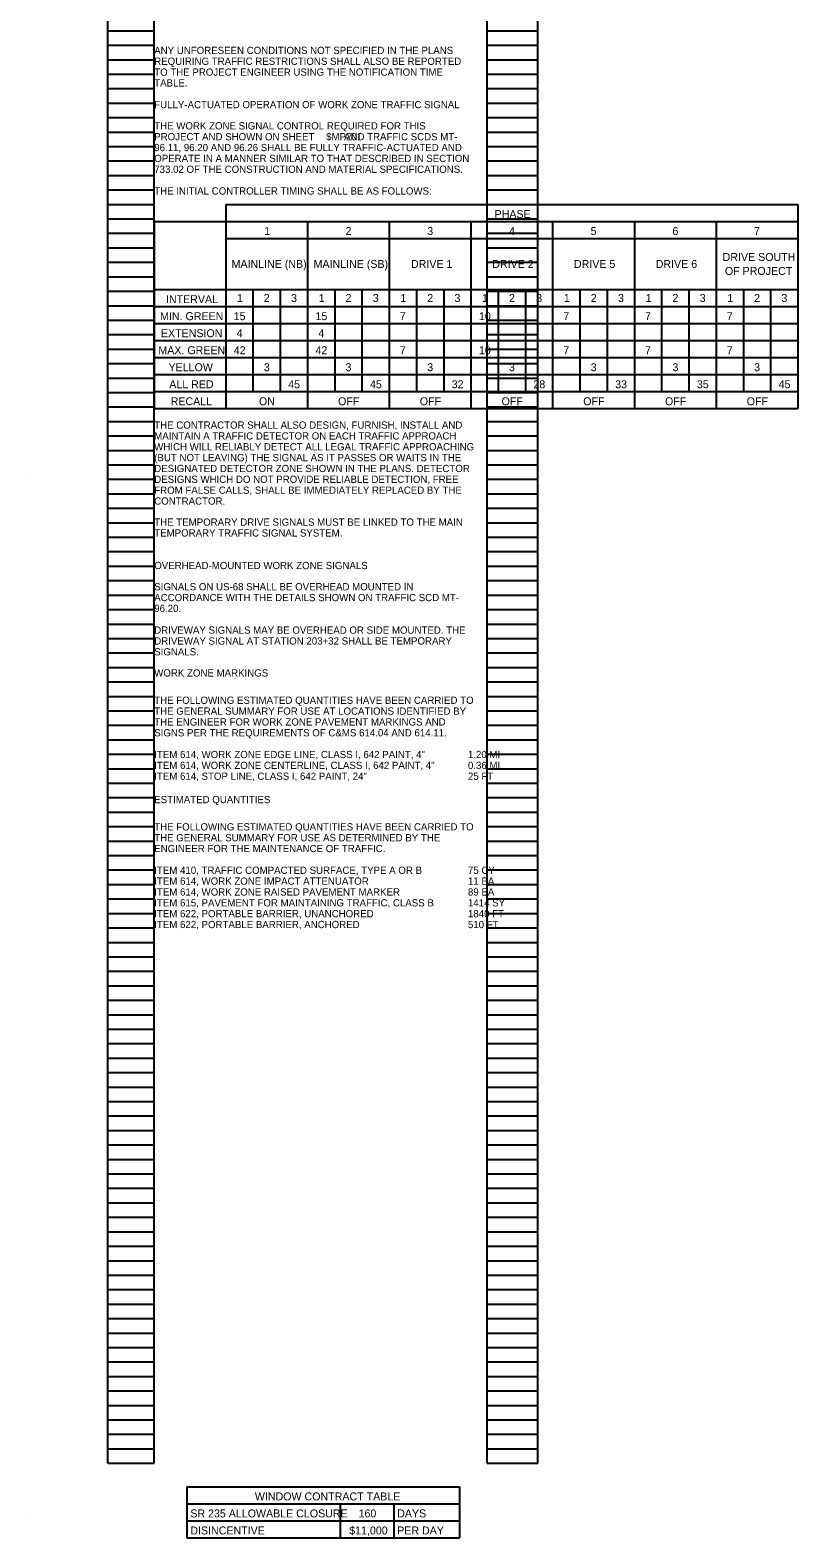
# Model space of a CAD drawing. Extents: x 11124 to 11156, y 1608 to 1730.
# Drawn here: x 11124.4 to 11139.25, y 1607.81 to 1636.98 of the extents above; entities that cross this region are included whole.
import ezdxf

# ---------------------------------------------------------------- set-up
doc = ezdxf.new("R2010")
doc.units = 0
for name, color, linetype in [('SC_Scratch1', 7, 'Continuous'), ('SH_Data', 7, 'Continuous'), ('SH_Text', 7, 'Continuous')]:
    doc.layers.add(name, color=color, linetype=linetype)

msp = doc.modelspace()

# ---------------------------------------------------------------- linework, layer by layer
at = {"layer": 'SC_Scratch1'}
for p, q in [((11125.896, 1629.409), (11125.896, 1649.569)), ((11126.796, 1629.409), (11126.796, 1649.569)), ((11133.236, 1629.409), (11133.236, 1649.569)), ((11134.216, 1629.409), (11134.216, 1649.569)), ((11125.896, 1636.969), (11126.796, 1636.969)), ((11133.236, 1636.969), (11134.216, 1636.969)), ((11125.896, 1636.689), (11126.796, 1636.689)), ((11133.236, 1636.689), (11134.216, 1636.689)), ((11125.896, 1636.409), (11126.796, 1636.409)), ((11133.236, 1636.409), (11134.216, 1636.409)), ((11125.896, 1636.129), (11126.796, 1636.129)), ((11133.236, 1636.129), (11134.216, 1636.129)), ((11125.896, 1635.849), (11126.796, 1635.849)), ((11125.896, 1635.569), (11126.796, 1635.569)), ((11133.236, 1635.849), (11134.216, 1635.849)), ((11133.236, 1635.569), (11134.216, 1635.569)), ((11125.896, 1635.289), (11126.796, 1635.289)), ((11133.236, 1635.289), (11134.216, 1635.289)), ((11125.896, 1635.009), (11126.796, 1635.009)), ((11133.236, 1635.009), (11134.216, 1635.009)), ((11125.896, 1634.729), (11126.796, 1634.729)), ((11133.236, 1634.729), (11134.216, 1634.729)), ((11125.896, 1634.449), (11126.796, 1634.449)), ((11133.236, 1634.449), (11134.216, 1634.449)), ((11125.896, 1634.169), (11126.796, 1634.169)), ((11133.236, 1634.169), (11134.216, 1634.169)), ((11125.896, 1633.889), (11126.796, 1633.889)), ((11133.236, 1633.889), (11134.216, 1633.889)), ((11125.896, 1633.609), (11126.796, 1633.609)), ((11133.236, 1633.609), (11134.216, 1633.609)), ((11125.896, 1633.329), (11126.796, 1633.329)), ((11133.236, 1633.329), (11134.216, 1633.329)), ((11125.896, 1633.049), (11126.796, 1633.049)), ((11133.236, 1633.049), (11134.216, 1633.049)), ((11125.896, 1632.769), (11126.796, 1632.769)), ((11133.236, 1632.769), (11134.216, 1632.769)), ((11125.896, 1632.489), (11126.796, 1632.489)), ((11133.236, 1632.489), (11134.216, 1632.489)), ((11125.896, 1632.209), (11126.796, 1632.209)), ((11133.236, 1632.209), (11134.216, 1632.209)), ((11125.896, 1631.929), (11126.796, 1631.929)), ((11133.236, 1631.929), (11134.216, 1631.929)), ((11125.896, 1631.649), (11126.796, 1631.649)), ((11133.236, 1631.649), (11134.216, 1631.649)), ((11125.896, 1631.369), (11126.796, 1631.369)), ((11133.236, 1631.369), (11134.216, 1631.369)), ((11125.896, 1631.089), (11126.796, 1631.089)), ((11133.236, 1631.089), (11134.216, 1631.089)), ((11125.896, 1630.809), (11126.796, 1630.809)), ((11133.236, 1630.809), (11134.216, 1630.809)), ((11125.896, 1630.529), (11126.796, 1630.529)), ((11133.236, 1630.529), (11134.216, 1630.529)), ((11125.896, 1630.249), (11126.796, 1630.249)), ((11133.236, 1630.249), (11134.216, 1630.249)), ((11125.896, 1629.969), (11126.796, 1629.969)), ((11133.236, 1629.969), (11134.216, 1629.969)), ((11125.896, 1629.689), (11126.796, 1629.689)), ((11133.236, 1629.689), (11134.216, 1629.689)), ((11125.896, 1629.409), (11126.796, 1629.409)), ((11125.896, 1609.249), (11125.896, 1629.409)), ((11125.896, 1629.409), (11126.796, 1629.409)), ((11126.796, 1609.249), (11126.796, 1629.409)), ((11133.236, 1629.409), (11134.216, 1629.409)), ((11133.236, 1609.249), (11133.236, 1629.409)), ((11133.236, 1629.409), (11134.216, 1629.409)), ((11134.216, 1609.249), (11134.216, 1629.409)), ((11125.896, 1629.129), (11126.796, 1629.129)), ((11125.896, 1628.849), (11126.796, 1628.849)), ((11133.236, 1629.129), (11134.216, 1629.129)), ((11133.236, 1628.849), (11134.216, 1628.849)), ((11125.896, 1628.569), (11126.796, 1628.569)), ((11133.236, 1628.569), (11134.216, 1628.569)), ((11124.396, 1628.429), (11124.396, 1628.429)), ((11125.896, 1628.289), (11126.796, 1628.289)), ((11133.236, 1628.289), (11134.216, 1628.289)), ((11125.896, 1628.009), (11126.796, 1628.009)), ((11133.236, 1628.009), (11134.216, 1628.009)), ((11125.896, 1627.729), (11126.796, 1627.729)), ((11133.236, 1627.729), (11134.216, 1627.729)), ((11125.896, 1627.449), (11126.796, 1627.449)), ((11133.236, 1627.449), (11134.216, 1627.449)), ((11125.896, 1627.169), (11126.796, 1627.169)), ((11133.236, 1627.169), (11134.216, 1627.169)), ((11125.896, 1626.889), (11126.796, 1626.889)), ((11133.236, 1626.889), (11134.216, 1626.889)), ((11125.896, 1626.609), (11126.796, 1626.609)), ((11133.236, 1626.609), (11134.216, 1626.609)), ((11125.896, 1626.329), (11126.796, 1626.329)), ((11133.236, 1626.329), (11134.216, 1626.329)), ((11125.896, 1626.049), (11126.796, 1626.049)), ((11133.236, 1626.049), (11134.216, 1626.049)), ((11125.896, 1625.769), (11126.796, 1625.769)), ((11133.236, 1625.769), (11134.216, 1625.769)), ((11125.896, 1625.489), (11126.796, 1625.489)), ((11133.236, 1625.489), (11134.216, 1625.489)), ((11125.896, 1625.209), (11126.796, 1625.209)), ((11133.236, 1625.209), (11134.216, 1625.209)), ((11125.896, 1624.929), (11126.796, 1624.929)), ((11133.236, 1624.929), (11134.216, 1624.929)), ((11125.896, 1624.649), (11126.796, 1624.649)), ((11133.236, 1624.649), (11134.216, 1624.649)), ((11125.896, 1624.369), (11126.796, 1624.369)), ((11133.236, 1624.369), (11134.216, 1624.369)), ((11125.896, 1624.089), (11126.796, 1624.089)), ((11133.236, 1624.089), (11134.216, 1624.089)), ((11125.896, 1623.809), (11126.796, 1623.809)), ((11133.236, 1623.809), (11134.216, 1623.809)), ((11125.896, 1623.529), (11126.796, 1623.529)), ((11133.236, 1623.529), (11134.216, 1623.529)), ((11125.896, 1623.249), (11126.796, 1623.249)), ((11133.236, 1623.249), (11134.216, 1623.249)), ((11125.896, 1622.969), (11126.796, 1622.969)), ((11133.236, 1622.969), (11134.216, 1622.969)), ((11125.896, 1622.689), (11126.796, 1622.689)), ((11133.236, 1622.689), (11134.216, 1622.689)), ((11125.896, 1622.409), (11126.796, 1622.409)), ((11133.236, 1622.409), (11134.216, 1622.409)), ((11125.896, 1622.129), (11126.796, 1622.129)), ((11125.896, 1621.849), (11126.796, 1621.849)), ((11133.236, 1622.129), (11134.216, 1622.129)), ((11133.236, 1621.849), (11134.216, 1621.849)), ((11125.896, 1621.569), (11126.796, 1621.569)), ((11133.236, 1621.569), (11134.216, 1621.569)), ((11125.896, 1621.289), (11126.796, 1621.289)), ((11133.236, 1621.289), (11134.216, 1621.289)), ((11125.896, 1621.009), (11126.796, 1621.009)), ((11133.236, 1621.009), (11134.216, 1621.009)), ((11125.896, 1620.729), (11126.796, 1620.729)), ((11133.236, 1620.729), (11134.216, 1620.729)), ((11125.896, 1620.449), (11126.796, 1620.449)), ((11133.236, 1620.449), (11134.216, 1620.449)), ((11125.896, 1620.169), (11126.796, 1620.169)), ((11133.236, 1620.169), (11134.216, 1620.169)), ((11125.896, 1619.889), (11126.796, 1619.889)), ((11133.236, 1619.889), (11134.216, 1619.889)), ((11125.896, 1619.609), (11126.796, 1619.609)), ((11133.236, 1619.609), (11134.216, 1619.609)), ((11125.896, 1619.329), (11126.796, 1619.329)), ((11133.236, 1619.329), (11134.216, 1619.329)), ((11125.896, 1619.049), (11126.796, 1619.049)), ((11133.236, 1619.049), (11134.216, 1619.049)), ((11125.896, 1618.769), (11126.796, 1618.769)), ((11133.236, 1618.769), (11134.216, 1618.769)), ((11125.896, 1618.489), (11126.796, 1618.489)), ((11133.236, 1618.489), (11134.216, 1618.489)), ((11125.896, 1618.209), (11126.796, 1618.209)), ((11133.236, 1618.209), (11134.216, 1618.209)), ((11125.896, 1617.929), (11126.796, 1617.929)), ((11133.236, 1617.929), (11134.216, 1617.929)), ((11125.896, 1617.649), (11126.796, 1617.649)), ((11133.236, 1617.649), (11134.216, 1617.649)), ((11125.896, 1617.369), (11126.796, 1617.369)), ((11133.236, 1617.369), (11134.216, 1617.369)), ((11125.896, 1617.089), (11126.796, 1617.089)), ((11133.236, 1617.089), (11134.216, 1617.089)), ((11125.896, 1616.809), (11126.796, 1616.809)), ((11133.236, 1616.809), (11134.216, 1616.809)), ((11125.896, 1616.529), (11126.796, 1616.529)), ((11133.236, 1616.529), (11134.216, 1616.529)), ((11125.896, 1616.249), (11126.796, 1616.249)), ((11133.236, 1616.249), (11134.216, 1616.249)), ((11125.896, 1615.969), (11126.796, 1615.969)), ((11133.236, 1615.969), (11134.216, 1615.969)), ((11125.896, 1615.689), (11126.796, 1615.689)), ((11133.236, 1615.689), (11134.216, 1615.689)), ((11125.896, 1615.409), (11126.796, 1615.409)), ((11133.236, 1615.409), (11134.216, 1615.409)), ((11125.896, 1615.129), (11126.796, 1615.129)), ((11125.896, 1614.849), (11126.796, 1614.849)), ((11133.236, 1615.129), (11134.216, 1615.129)), ((11133.236, 1614.849), (11134.216, 1614.849)), ((11125.896, 1614.569), (11126.796, 1614.569)), ((11133.236, 1614.569), (11134.216, 1614.569)), ((11125.896, 1614.289), (11126.796, 1614.289)), ((11133.236, 1614.289), (11134.216, 1614.289)), ((11125.896, 1614.009), (11126.796, 1614.009)), ((11133.236, 1614.009), (11134.216, 1614.009)), ((11125.896, 1613.729), (11126.796, 1613.729)), ((11133.236, 1613.729), (11134.216, 1613.729)), ((11125.896, 1613.449), (11126.796, 1613.449)), ((11133.236, 1613.449), (11134.216, 1613.449)), ((11125.896, 1613.169), (11126.796, 1613.169)), ((11133.236, 1613.169), (11134.216, 1613.169)), ((11125.896, 1612.889), (11126.796, 1612.889)), ((11133.236, 1612.889), (11134.216, 1612.889)), ((11125.896, 1612.609), (11126.796, 1612.609)), ((11133.236, 1612.609), (11134.216, 1612.609)), ((11125.896, 1612.329), (11126.796, 1612.329)), ((11133.236, 1612.329), (11134.216, 1612.329)), ((11125.896, 1612.049), (11126.796, 1612.049)), ((11133.236, 1612.049), (11134.216, 1612.049)), ((11125.896, 1611.769), (11126.796, 1611.769)), ((11133.236, 1611.769), (11134.216, 1611.769)), ((11125.896, 1611.489), (11126.796, 1611.489)), ((11133.236, 1611.489), (11134.216, 1611.489)), ((11125.896, 1611.209), (11126.796, 1611.209)), ((11133.236, 1611.209), (11134.216, 1611.209)), ((11125.896, 1610.929), (11126.796, 1610.929)), ((11133.236, 1610.929), (11134.216, 1610.929)), ((11125.896, 1610.649), (11126.796, 1610.649)), ((11133.236, 1610.649), (11134.216, 1610.649)), ((11125.896, 1610.369), (11126.796, 1610.369)), ((11133.236, 1610.369), (11134.216, 1610.369)), ((11125.896, 1610.089), (11126.796, 1610.089)), ((11133.236, 1610.089), (11134.216, 1610.089)), ((11125.896, 1609.809), (11126.796, 1609.809)), ((11133.236, 1609.809), (11134.216, 1609.809)), ((11125.896, 1609.529), (11126.796, 1609.529)), ((11133.236, 1609.529), (11134.216, 1609.529)), ((11125.896, 1609.249), (11126.796, 1609.249)), ((11133.236, 1609.249), (11134.216, 1609.249)), ((11124.396, 1608.269), (11124.396, 1608.269))]:
    msp.add_line(p, q, dxfattribs=at)
at = {"layer": 'SH_Data'}
for p, q in [((11128.179, 1633.609), (11139.247, 1633.609)), ((11128.179, 1633.609), (11128.179, 1629.656)), ((11139.247, 1633.609), (11139.247, 1629.656)), ((11126.796, 1633.279), (11139.247, 1633.279)), ((11126.796, 1633.279), (11126.796, 1629.656)), ((11129.76, 1633.279), (11129.76, 1629.656)), ((11131.342, 1633.279), (11131.342, 1629.656)), ((11132.923, 1633.279), (11132.923, 1629.656)), ((11134.504, 1633.279), (11134.504, 1629.656)), ((11136.085, 1633.279), (11136.085, 1629.656)), ((11137.666, 1633.279), (11137.666, 1629.656)), ((11128.179, 1632.95), (11139.247, 1632.95)), ((11126.796, 1631.962), (11139.247, 1631.962)), ((11128.706, 1631.962), (11128.706, 1629.985)), ((11129.233, 1631.962), (11129.233, 1629.985)), ((11130.287, 1631.962), (11130.287, 1629.985)), ((11130.814, 1631.962), (11130.814, 1629.985)), ((11131.869, 1631.962), (11131.869, 1629.985)), ((11132.396, 1631.962), (11132.396, 1629.985)), ((11133.45, 1631.962), (11133.45, 1629.985)), ((11133.977, 1631.962), (11133.977, 1629.985)), ((11135.031, 1631.962), (11135.031, 1629.985)), ((11135.558, 1631.962), (11135.558, 1629.985)), ((11136.612, 1631.962), (11136.612, 1629.985)), ((11137.139, 1631.962), (11137.139, 1629.985)), ((11138.193, 1631.962), (11138.193, 1629.985)), ((11138.72, 1631.962), (11138.72, 1629.985)), ((11126.796, 1631.632), (11139.247, 1631.632)), ((11126.796, 1631.303), (11139.247, 1631.303)), ((11126.796, 1630.974), (11139.247, 1630.974)), ((11126.796, 1630.644), (11139.247, 1630.644)), ((11126.796, 1630.315), (11139.247, 1630.315)), ((11126.796, 1629.985), (11139.247, 1629.985)), ((11126.796, 1629.656), (11139.247, 1629.656)), ((11127.428, 1608.794), (11132.699, 1608.794)), ((11127.428, 1608.794), (11127.428, 1607.805)), ((11132.699, 1608.794), (11132.699, 1607.805)), ((11127.428, 1608.464), (11132.699, 1608.464)), ((11130.393, 1608.464), (11130.393, 1607.805)), ((11131.431, 1608.464), (11131.431, 1607.805)), ((11127.428, 1608.135), (11132.699, 1608.135)), ((11127.428, 1607.805), (11132.699, 1607.805))]:
    msp.add_line(p, q, dxfattribs=at)

# ---------------------------------------------------------------- texts
at = {"layer": 'SH_Text'}
for s, height, p in [('ANY UNFORESEEN CONDITIONS NOT SPECIFIED IN THE PLANS ', 0.14, (11126.796, 1636.519)), ('REQUIRING TRAFFIC RESTRICTIONS SHALL ALSO BE REPORTED ', 0.14, (11126.796, 1636.309)), ('TO THE PROJECT ENGINEER USING THE NOTIFICATION TIME ', 0.14, (11126.796, 1636.099)), ('TABLE.', 0.14, (11126.796, 1635.889)), ('FULLY-ACTUATED OPERATION OF WORK ZONE TRAFFIC SIGNAL', 0.14, (11126.796, 1635.469)), ('THE WORK ZONE SIGNAL CONTROL REQUIRED FOR THIS ', 0.14, (11126.796, 1635.059)), ('PROJECT AND SHOWN ON SHEET           AND TRAFFIC SCDS MT-', 0.14, (11126.796, 1634.849)), ('$MP201', 0.14, (11130.122, 1634.849)), ('96.11, 96.20 AND 96.26 SHALL BE FULLY TRAFFIC-ACTUATED AND ', 0.14, (11126.796, 1634.639)), ('OPERATE IN A MANNER SIMILAR TO THAT DESCRIBED IN SECTION ', 0.14, (11126.796, 1634.429)), ('733.02 OF THE CONSTRUCTION AND MATERIAL SPECIFICATIONS. ', 0.14, (11126.796, 1634.219)), ('THE INITIAL CONTROLLER TIMING SHALL BE AS FOLLOWS:', 0.14, (11126.796, 1633.799)), ('PHASE', 0.154, (11133.381, 1633.345)), ('1', 0.154, (11128.923, 1633.016)), ('2', 0.154, (11130.497, 1633.016)), ('3', 0.154, (11132.078, 1633.016)), ('4', 0.154, (11133.661, 1633.016)), ('5', 0.154, (11135.239, 1633.016)), ('6', 0.154, (11136.821, 1633.016)), ('7', 0.154, (11138.399, 1633.016)), ('DRIVE SOUTH ', 0.154, (11137.792, 1632.514)), ('MAINLINE (NB)', 0.154, (11128.292, 1632.379)), ('MAINLINE (SB)', 0.154, (11129.879, 1632.379)), ('DRIVE 1', 0.154, (11131.763, 1632.379)), ('DRIVE 2', 0.154, (11133.336, 1632.379)), ('DRIVE 5', 0.154, (11134.916, 1632.379)), ('DRIVE 6', 0.154, (11136.498, 1632.379)), ('OF PROJECT', 0.154, (11137.836, 1632.244)), ('INTERVAL', 0.154, (11127.024, 1631.698)), ('1', 0.154, (11128.396, 1631.72)), ('2', 0.154, (11128.915, 1631.72)), ('3', 0.154, (11129.443, 1631.72)), ('1', 0.154, (11129.978, 1631.72)), ('2', 0.154, (11130.497, 1631.72)), ('3', 0.154, (11131.024, 1631.72)), ('1', 0.154, (11131.559, 1631.72)), ('2', 0.154, (11132.078, 1631.72)), ('3', 0.154, (11132.605, 1631.72)), ('1', 0.154, (11133.14, 1631.72)), ('2', 0.154, (11133.659, 1631.72)), ('3', 0.154, (11134.186, 1631.72)), ('1', 0.154, (11134.721, 1631.72)), ('2', 0.154, (11135.24, 1631.72)), ('3', 0.154, (11135.768, 1631.72)), ('1', 0.154, (11136.302, 1631.72)), ('2', 0.154, (11136.821, 1631.72)), ('3', 0.154, (11137.349, 1631.72)), ('1', 0.154, (11137.883, 1631.72)), ('2', 0.154, (11138.402, 1631.72)), ('3', 0.154, (11138.93, 1631.72)), ('MIN. GREEN', 0.154, (11126.909, 1631.369)), ('15', 0.154, (11128.333, 1631.369)), ('15', 0.154, (11129.915, 1631.369)), ('7', 0.154, (11131.547, 1631.369)), ('10', 0.154, (11133.078, 1631.369)), ('7', 0.154, (11134.71, 1631.369)), ('7', 0.154, (11136.291, 1631.369)), ('7', 0.154, (11137.872, 1631.369)), ('EXTENSION', 0.154, (11126.925, 1631.039)), ('4', 0.154, (11128.39, 1631.039)), ('4', 0.154, (11129.971, 1631.039)), ('MAX. GREEN', 0.154, (11126.876, 1630.71)), ('42', 0.154, (11128.335, 1630.71)), ('42', 0.154, (11129.916, 1630.71)), ('7', 0.154, (11131.547, 1630.71)), ('10', 0.154, (11133.078, 1630.71)), ('7', 0.154, (11134.71, 1630.71)), ('7', 0.154, (11136.291, 1630.71)), ('7', 0.154, (11137.872, 1630.71)), ('YELLOW', 0.154, (11127.072, 1630.381)), ('3', 0.154, (11128.916, 1630.381)), ('3', 0.154, (11130.497, 1630.381)), ('3', 0.154, (11132.078, 1630.381)), ('3', 0.154, (11133.659, 1630.381)), ('3', 0.154, (11135.241, 1630.381)), ('3', 0.154, (11136.822, 1630.381)), ('3', 0.154, (11138.403, 1630.381)), ('ALL RED', 0.154, (11127.087, 1630.051)), ('45', 0.154, (11129.388, 1630.051)), ('45', 0.154, (11130.969, 1630.051)), ('32', 0.154, (11132.551, 1630.051)), ('28', 0.154, (11134.132, 1630.051)), ('33', 0.154, (11135.714, 1630.051)), ('35', 0.154, (11137.294, 1630.051)), ('45', 0.154, (11138.875, 1630.051)), ('RECALL', 0.154, (11127.114, 1629.722)), ('ON', 0.154, (11128.822, 1629.722)), ('OFF', 0.154, (11130.353, 1629.722)), ('OFF', 0.154, (11131.934, 1629.722)), ('OFF', 0.154, (11133.515, 1629.722)), ('OFF', 0.154, (11135.096, 1629.722)), ('OFF', 0.154, (11136.677, 1629.722)), ('OFF', 0.154, (11138.258, 1629.722)), ('THE CONTRACTOR SHALL ALSO DESIGN, FURNISH, INSTALL AND ', 0.14, (11126.796, 1629.269)), ('MAINTAIN A TRAFFIC DETECTOR ON EACH TRAFFIC APPROACH ', 0.14, (11126.796, 1629.059)), ('WHICH WILL RELIABLY DETECT ALL LEGAL TRAFFIC APPROACHING ', 0.14, (11126.796, 1628.849)), ('(BUT NOT LEAVING) THE SIGNAL AS IT PASSES OR WAITS IN THE ', 0.14, (11126.796, 1628.639)), ('DESIGNATED DETECTOR ZONE SHOWN IN THE PLANS. DETECTOR ', 0.14, (11126.796, 1628.429)), ('DESIGNS WHICH DO NOT PROVIDE RELIABLE DETECTION, FREE ', 0.14, (11126.796, 1628.219)), ('FROM FALSE CALLS, SHALL BE IMMEDIATELY REPLACED BY THE ', 0.14, (11126.796, 1628.009)), ('CONTRACTOR.', 0.14, (11126.796, 1627.799)), ('THE TEMPORARY DRIVE SIGNALS MUST BE LINKED TO THE MAIN ', 0.14, (11126.796, 1627.391)), ('TEMPORARY TRAFFIC SIGNAL SYSTEM.', 0.14, (11126.796, 1627.181)), ('OVERHEAD-MOUNTED WORK ZONE SIGNALS', 0.14, (11126.796, 1626.551)), ('SIGNALS ON US-68 SHALL BE OVERHEAD MOUNTED IN ', 0.14, (11126.796, 1626.141)), ('ACCORDANCE WITH THE DETAILS SHOWN ON TRAFFIC SCD MT-', 0.14, (11126.796, 1625.931)), ('96.20.', 0.14, (11126.796, 1625.721)), ('DRIVEWAY SIGNALS MAY BE OVERHEAD OR SIDE MOUNTED. THE ', 0.14, (11126.796, 1625.301)), ('DRIVEWAY SIGNAL AT STATION 203+32 SHALL BE TEMPORARY ', 0.14, (11126.796, 1625.091)), ('SIGNALS.', 0.14, (11126.796, 1624.881)), ('WORK ZONE MARKINGS', 0.14, (11126.796, 1624.472)), ('THE FOLLOWING ESTIMATED QUANTITIES HAVE BEEN CARRIED TO ', 0.14, (11126.796, 1623.944)), ('THE GENERAL SUMMARY FOR USE AT LOCATIONS IDENTIFIED BY ', 0.14, (11126.796, 1623.734)), ('THE ENGINEER FOR WORK ZONE PAVEMENT MARKINGS AND ', 0.14, (11126.796, 1623.524)), ('SIGNS PER THE REQUIREMENTS OF C&MS 614.04 AND 614.11.', 0.14, (11126.796, 1623.314)), ('ITEM 614, WORK ZONE EDGE LINE, CLASS I, 642 PAINT, 4"', 0.14, (11126.796, 1622.894)), ('1.20 MI', 0.14, (11132.865, 1622.894)), ('ITEM 614, WORK ZONE CENTERLINE, CLASS I, 642 PAINT, 4"', 0.14, (11126.796, 1622.684)), ('0.36 MI', 0.14, (11132.865, 1622.684)), ('ITEM 614, STOP LINE, CLASS I, 642 PAINT, 24"', 0.14, (11126.796, 1622.474)), ('25 FT', 0.14, (11132.865, 1622.474)), ('ESTIMATED QUANTITIES', 0.14, (11126.796, 1622.022)), ('THE FOLLOWING ESTIMATED QUANTITIES HAVE BEEN CARRIED TO ', 0.14, (11126.796, 1621.494)), ('THE GENERAL SUMMARY FOR USE AS DETERMINED BY THE ', 0.14, (11126.796, 1621.284)), ('ENGINEER FOR THE MAINTENANCE OF TRAFFIC.', 0.14, (11126.796, 1621.074)), ('ITEM 410, TRAFFIC COMPACTED SURFACE, TYPE A OR B', 0.14, (11126.796, 1620.654)), ('75 CY', 0.14, (11132.865, 1620.654)), ('ITEM 614, WORK ZONE IMPACT ATTENUATOR', 0.14, (11126.796, 1620.444)), ('11 EA', 0.14, (11132.865, 1620.444)), ('ITEM 614, WORK ZONE RAISED PAVEMENT MARKER', 0.14, (11126.796, 1620.234)), ('ITEM 615, PAVEMENT FOR MAINTAINING TRAFFIC, CLASS B', 0.14, (11126.796, 1620.024)), ('89 EA', 0.14, (11132.865, 1620.234)), ('1414 SY', 0.14, (11132.865, 1620.024)), ('ITEM 622, PORTABLE BARRIER, UNANCHORED', 0.14, (11126.796, 1619.814)), ('1840 FT', 0.14, (11132.865, 1619.814)), ('ITEM 622, PORTABLE BARRIER, ANCHORED', 0.14, (11126.796, 1619.604)), ('510 FT', 0.14, (11132.865, 1619.604)), ('WINDOW CONTRACT TABLE', 0.154, (11128.743, 1608.53)), ('SR 235 ALLOWABLE CLOSURE', 0.154, (11127.494, 1608.201)), ('160', 0.154, (11130.749, 1608.201)), ('DAYS', 0.154, (11131.496, 1608.201)), ('DISINCENTIVE', 0.154, (11127.494, 1607.871)), ('$11,000', 0.154, (11130.568, 1607.871)), ('PER DAY', 0.154, (11131.496, 1607.871))]:
    msp.add_text(s, height=height, dxfattribs=at).set_placement(p)

doc.saveas('drawing.dxf')
